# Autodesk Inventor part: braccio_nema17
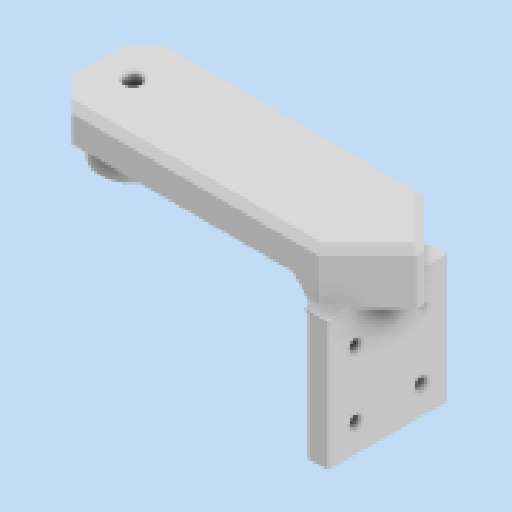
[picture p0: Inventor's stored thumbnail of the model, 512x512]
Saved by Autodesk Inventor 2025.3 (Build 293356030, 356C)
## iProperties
Created: 2025-11
Part Number: braccio_nema17
Material: Generico
Document SubType Name: Modeling
Designer: R5800u
Density: 1 g/cm^3
Appearance: Default
Author: R5800u
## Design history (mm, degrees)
sketch "Schizzo1"
  geometry: L1 (2, 1.582)-(2, -1.582); C1 r 10 at (0, 0); A1 r 2.55 centre (0, 0) between (2, 1.582) and (2, -1.582); 1 further point
  constraints: 2 centre point, 2 coincident, 2 end point, 2 point on circle, 1 vertical
  dimensions: "d0" = 20 diameter of C1; "d1" = 5.1 diameter of A1; "d2" = 2 distance from line of point (0, 0) L1
extrude "Estrusione1" new body sketch "Schizzo1" distance "d3" = 20; taper "d4" = 0 deg
sketch "Schizzo2"
  geometry: L1 (-12.5, -16)-(87.5, -16); L2 (87.5, -16)-(87.5, 16); L3 (87.5, 16)-(-12.5, 16); L4 (-12.5, 16)-(-12.5, -16); L5 (0, 0)-(107, 0) reference; C1 r 10 at (0, 0) reference; C2 r 2.55 at (0, 0) reference; 1 further point
  constraints: 10 end point, 3 horizontal, 2 parallel, 1 perpendicular, 1 other
  dimensions: "d5" = 100 distance of L3.end L2.end
extrude "Estrusione2" join sketch "Schizzo2" distance "d6" = 10; taper "d7" = 0 deg
sketch "Schizzo3"
  geometry: L1 (18.5, -5)-(13.5, -5); L2 (13.5, -5)-(13.5, -15); L3 (13.5, -15)-(18.5, -15); L4 (18.5, -15)-(18.5, -5); L5 (6, -10)-(26, -10) reference; L6 (18.5, -5)-(13.5, -15); L7 (13.5, -5)-(18.5, -15); L8 (32, -10)-(0, -10) reference; 4 further points
  constraints: 12 end point, 3 midpoint, 2 parallel, 1 horizontal, 1 perpendicular
  dimensions: "d8" = 5 distance of L3.end L2.end
extrude "Estrusione3" join sketch "Schizzo3" stored distance "d9" = 10; taper "d10" = 0 deg
chamfer "Smusso1" distance "d11" = 6; stored, may be unused: second distance "d12" = 2, angle "d13" = 45 deg
sketch "Schizzo4"
  geometry: L1 (-6.5, -16)-(87.5, -16) reference; L2 (77.5, -16)-(77.5, 16); L3 (87.5, -16)-(87.5, -2.5) reference; L4 (87.5, 16)-(-6.5, 16) reference; L5 (77.5, -16)-(87.5, -16); L6 (87.5, -16)-(87.5, 16); L7 (87.5, 16)-(77.5, 16); L8 (77.5, 16)-(77.5, -16); 2 further points
  constraints: 10 end point, 2 parallel, 1 horizontal, 1 perpendicular, 1 point on line, 1 vertical
  dimensions: "d14" = 10 distance between parallel lines of L3 L2
node "Piano di lavoro1"
extrude "Estrusione4" join sketch "Schizzo4" stored distance "d15" = 10; taper "d16" = 0 deg
sketch "Schizzo5"
  geometry: L1 (77.5, -16)-(77.5, -2.5) reference; L2 (-6.5, 16)-(87.5, 16) reference; L3 (77.5, -16)-(69.5, -16); L4 (69.5, -16)-(69.5, 16); L5 (69.5, 16)-(77.5, 16); L6 (77.5, 16)-(77.5, -16); 3 further points
  constraints: 8 end point, 2 parallel, 1 horizontal, 1 perpendicular, 1 point on line
  dimensions: "d17" = 8 distance of L4.end L5.end
node "Piano di lavoro2"
extrude "Estrusione5" join sketch "Schizzo5" stored distance "d18" = 10; taper "d19" = 0 deg
sketch "Schizzo6"
  geometry: C1 r 1.45 at (6, -16.1) reference; C2 r 1.45 at (26, -16.1) reference; C3 r 1.45 at (6, -36.1) reference; C4 r 1.45 at (26, -36.1) reference; 1 further point
hole "Foro1" sketch "Schizzo6" at (6, -16.1), (26, -16.1), (6, -36.1), (26, -36.1) diameter "d20" = 3.2; stored, may be unused: countersink angle "d24" = 90 deg, drill point angle "d26" = 118 deg; dims "d21" = 6, "d22" = 6.5, "d23" = 3.4, "d25" = 12
chamfer "Smusso2" distance "d27" = 2; stored, may be unused: second distance "d28" = 2, angle "d29" = 45 deg
chamfer "Smusso3" distance "d30" = 5; stored, may be unused: second distance "d31" = 2, angle "d32" = 45 deg
sketch "Schizzo7"
  geometry: L1 (-2, 1.582)-(-2, -1.582); A1 r 2.55 centre (0, 0) between (-2, 1.582) and (-2, -1.582) reference; 3 further points
  constraints: 2 end point, 1 point on circle, 1 vertical, 2 other
  dimensions: "d33" = 2 distance from line of point (0, 0) L1
extrude "Estrusione6" join sketch "Schizzo7" distance "d34" = 17; taper "d35" = 0 deg
chamfer "Smusso4" distance "d36" = 2; stored, may be unused: second distance "d37" = 2, angle "d38" = 45 deg
chamfer "Smusso5" distance "d39" = 15; stored, may be unused: second distance "d40" = 2, angle "d41" = 45 deg
chamfer "Smusso6" distance "d42" = 2; stored, may be unused: second distance "d43" = 2, angle "d44" = 45 deg
sketch "Schizzo8"
  geometry: L1 (0, 14)-(94, 14) reference; L2 (0, 14)-(0, 0) reference; L3 (10, 0)-(0, 0) reference; L4 (10, 0)-(10, -39) reference; L5 (10, -39)-(16, -39) reference; L6 (18, -37)-(16, -39) reference; L7 (18, 1)-(18, -37) reference; L8 (23, 6)-(18, 1) reference; L9 (94, 6)-(23, 6) reference; L10 (94, 14)-(94, 6) reference; L11 (10, 0)-(18, 0); 1 further point
  constraints: 2 end point, 1 perpendicular, 1 point on line
extrude "Estrusione7" join sketch "Schizzo8" distance "d48" = 2; taper "d49" = 0 deg
mirror "Speculare1"
chamfer "Smusso8" distance "d50" = 15; stored, may be unused: second distance "d51" = 2, angle "d52" = 45 deg
fillet "Raccordo1" dims "d53" = 1.99
chamfer "Smusso9" distance "d54" = 2; stored, may be unused: second distance "d55" = 2, angle "d56" = 45 deg
chamfer "Smusso10" distance "d57" = 2; stored, may be unused: second distance "d58" = 2, angle "d59" = 45 deg
chamfer "Smusso11" distance "d60" = 2; stored, may be unused: second distance "d61" = 2, angle "d62" = 45 deg
node "Solido1"
node "Linea chiusa proiettata1"
node "Riferimento1"
node "Riferimento2"
node "Riferimento3"
node "Riferimento4"
node "Linea chiusa proiettata2"
